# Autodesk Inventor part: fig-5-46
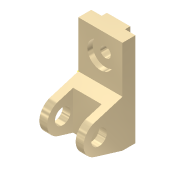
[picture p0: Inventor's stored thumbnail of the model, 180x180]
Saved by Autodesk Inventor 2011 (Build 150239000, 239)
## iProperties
Shininess: 65.0
Angle Display Precision: 2
Document Length Units: 11269
Document Angle Units: 11279
Document Time Units: 11290
Document Mass Units: 11283
Document Length Units Precision: 3
Document Angle Units Precision: 2
Created: 2001-11
Part Number: fig-5-46
Document SubType Name: Modeling
Designer: Renu Muthoo
Density: 1 g/cm^3
Density: 0.0
Volumn: 0.0
Area: 0.0
PropertySet Name: Model Information
Control State: 0
Master: False
Checked Out: False
Author: Renu Muthoo
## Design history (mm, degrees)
node "Sketch1"
sketch "Sketch2"
  geometry: L1 (33.257, 104.664)-(33.257, -75.336); L2 (33.257, -75.336)-(8.257, -75.336); L3 (8.257, -75.336)-(-45.451, -59.045); L4 (-45.451, -1.628)-(8.257, 14.664); L5 (8.257, 14.664)-(8.257, 104.664); L6 (8.257, 104.664)-(33.257, 104.664); C1 r 15 at (-36.743, -30.336); A1 r 30 centre (-36.743, -30.336) between (-45.451, -1.628) and (-45.451, -59.045)
  constraints: 12 end point, 2 centre point, 2 equal length, 2 parallel, 2 point on circle, 2 tangent, 1 coincident, 1 perpendicular, 1 vertical
  dimensions: "d0" = 180 distance of L1.start L1.end; "d1" = 30 radius of A1; "d2" = 25 distance of L5.end L1.start; "d3" = 45 distance from line of L2 A1.centre; "d4" = 70 distance from line of L1 A1.centre; "d5" = 30 diameter of C1
extrude "Extrusion1" new body sketch "Sketch2" distance "d6" = 85; taper "d7" = 0 deg
workplane "Work Plane1"
sketch "Sketch3"
  geometry: L1 (15, 62.364)-(70, 62.364); L2 (70, 62.364)-(70, -52.386); L3 (70, -52.386)-(15, -52.386); L4 (15, -52.386)-(15, 62.364); L5 (0, -45)-(0, -28.708) reference
  constraints: 8 end point, 2 parallel, 1 horizontal, 1 perpendicular
  dimensions: "d8" = 55 distance of L1.start L1.end; "d9" = 15 distance between parallel lines of L5 L4
extrude "Extrusion2" cut sketch "Sketch3" distance "d10" = 50; taper "d11" = 0 deg
sketch "Sketch4"
  geometry: L1 (0, 25)-(85, 25) reference; L2 (0, 0)-(0, 25) reference; L3 (20, 25)-(65, 25); L4 (65, 25)-(65, 35); L5 (65, 35)-(20, 35); L6 (20, 35)-(20, 25)
  constraints: 8 end point, 2 parallel, 1 horizontal, 1 perpendicular, 1 point on line
  dimensions: "d12" = 45 distance of L4.end L5.end; "d13" = 10 distance of L3.end L4.end; "d14" = 20 distance between parallel lines of L2 L6
extrude "Extrusion3" join sketch "Sketch4" stored distance "d15" = 50; taper "d16" = 0 deg
sketch "Sketch5"
  geometry: L1 (85, 0)-(85, 90) reference; L2 (0, 90)-(85, 90) reference; 1 further point
  dimensions: "d17" = 42 distance from line of L2 point (42.5, 48); "d18" = 42.5 distance from line of L1 point (42.5, 48)
hole "Hole1" sketch "Sketch5" at (42.5, 48) diameter "d19" = 20; stored, may be unused: countersink angle "d23" = 82 deg, drill point angle "d25" = 118 deg; dims "d20" = 6, "d21" = 50, "d22" = 10, "d24" = 8
workpoint "Work Point5"
body "Solid1"
